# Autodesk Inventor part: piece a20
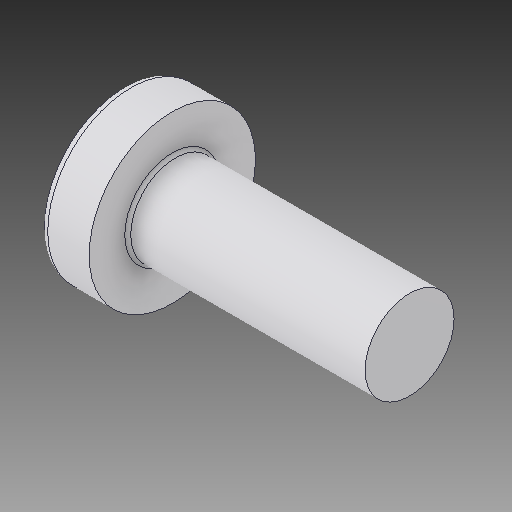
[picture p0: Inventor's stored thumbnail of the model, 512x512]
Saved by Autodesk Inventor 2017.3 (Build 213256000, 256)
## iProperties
Created: 1999-08
Part Number: piece a20
Material: solidworks materials|Alliage 7079|22
Document SubType Name: Modeling
Designer: ficho
Appearance: 227,227,233
Author: ficho
Sending System: SolidWorks 2009
Last Author: christophe
Last Saved: 2011-01-17
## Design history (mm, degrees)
feature "RecessCore"
node "Solide1"
